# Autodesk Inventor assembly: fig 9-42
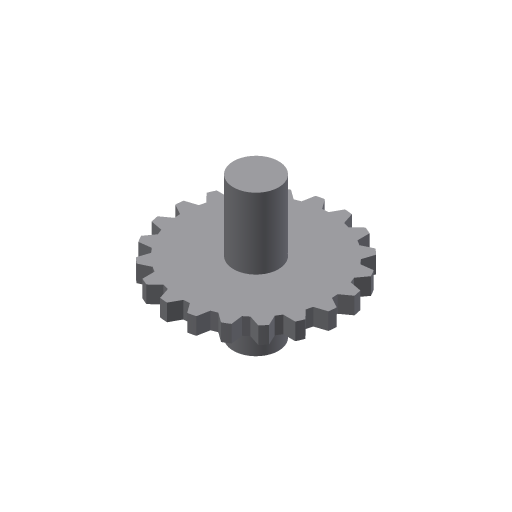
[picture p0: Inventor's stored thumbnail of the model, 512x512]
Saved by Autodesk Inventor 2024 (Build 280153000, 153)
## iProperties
Created: 2013-07
Part Number: fig 9-42
Document SubType Name: Assembly
Designer: CADCIM
Author: CADCIM
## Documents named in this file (3)
- D:\PROJECTS\Project 2023\RESOURCES INVENTOR 2024\RESOURCES INVENTOR 2024\Inventor_2023_Part\Inventor_2024_Part\c09_Inv_2024_prt\fig 9-43.iam
- D:\PROJECTS\Project 2023\RESOURCES INVENTOR 2024\RESOURCES INVENTOR 2024\Inventor_2023_Part\Inventor_2024_Part\c09_Inv_2024_prt\13.ipt
- D:\PROJECTS\Project 2023\RESOURCES INVENTOR 2024\RESOURCES INVENTOR 2024\Inventor_2023_Part\Inventor_2024_Part\c09_Inv_2024_prt\14.ipt
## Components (2 placed, 2 different names)
1. 13:1 — Rotational:1
2. 14:1 — Rotational:1
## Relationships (1: RevoluteJoint 1)
- Rotational:1 [RevoluteJoint]: 13:1 ↔ 14:1
